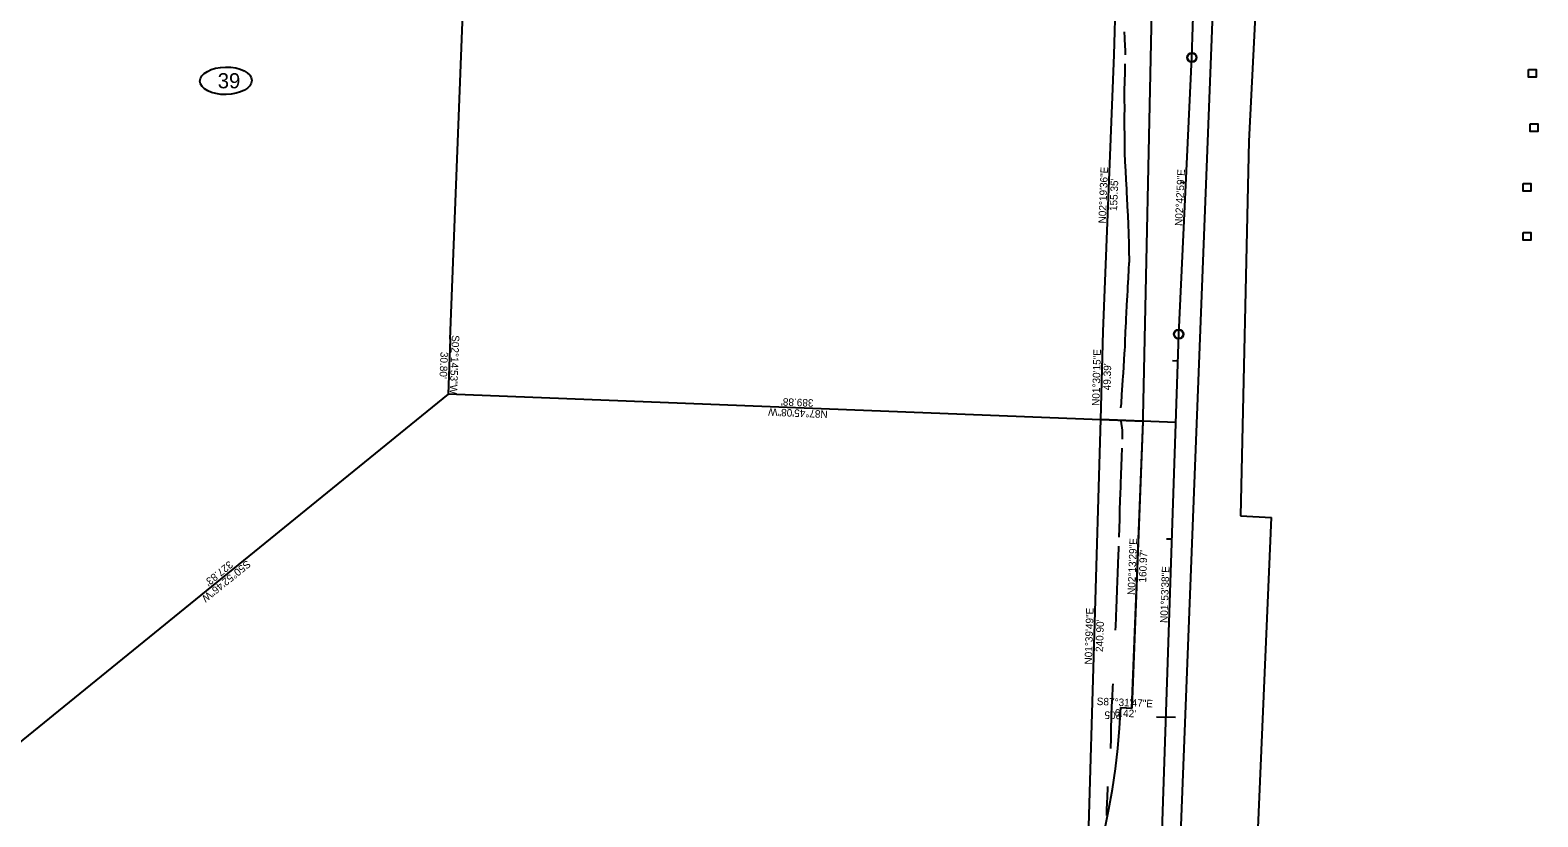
# Model space of a CAD drawing. Extents: x 1145508 to 2262867, y -3126236 to 2021677.
# Drawn here: x 1151042 to 1151887, y 2019521 to 2019963 of the extents above; entities that cross this region are included whole.
import ezdxf

# ---------------------------------------------------------------- set-up
doc = ezdxf.new("R2010")
doc.units = 0
for name, color, linetype in [('DSN_RDWY_Alignment', 7, 'Continuous'), ('DSN_RDWY_Alignment Annotation', 7, 'Continuous'), ('DSN_RDWY_Const Limits', 7, 'Continuous'), ('DSN_ROW_Annotation', 7, 'Continuous'), ('DSN_ROW_Esmnt', 7, 'Continuous'), ('DSN_ROW_Line-Annotation', 7, 'Continuous'), ('DSN_ROW_Prop-Line', 7, 'Continuous'), ('E_Const Align', 7, 'Continuous'), ('EX_PROPERTY', 7, 'Continuous'), ('EX_ROW', 7, 'Continuous'), ('EX_ROW_ANNOT', 7, 'Continuous'), ('EX_SECTION', 7, 'Continuous')]:
    doc.layers.add(name, color=color, linetype=linetype)

msp = doc.modelspace()

# ---------------------------------------------------------------- linework, layer by layer
at = {"layer": 'DSN_RDWY_Alignment'}
for centre in [(1151693.25, 2019947.42), (1151685.88, 2019792.22)]:
    msp.add_circle(centre, 2.5, dxfattribs=at)
at = {"layer": 'DSN_RDWY_Alignment Annotation'}
for p, q in [((1151693.25, 2019947.42), (1151693.25, 2019947.42)), ((1151686.92, 2019877.38), (1151689.92, 2019877.24)), ((1151685.88, 2019792.22), (1151685.88, 2019792.22)), ((1151682.39, 2019777.44), (1151685.39, 2019777.34)), ((1151679.09, 2019677.49), (1151682.09, 2019677.4)), ((1151673.45, 2019577.63), (1151684.06, 2019577.28))]:
    msp.add_line(p, q, dxfattribs=at)
for centre in [(1151693.25, 2019947.42), (1151685.88, 2019792.22)]:
    msp.add_circle(centre, 2.67, dxfattribs=at)
at = {"layer": 'DSN_RDWY_Const Limits'}
for points in [[(1151656.11, 2019948.92), (1151656.1, 2019949.18), (1151655.97, 2019951.85), (1151655.96, 2019952.12), (1151655.91, 2019953.37), (1151655.61, 2019958.38), (1151655.45, 2019961.72)], [(1151653.4, 2019750.97), (1151653.73, 2019753.37), (1151654.04, 2019758.37), (1151654.35, 2019763.36), (1151654.59, 2019766.67), (1151654.6, 2019766.87), (1151654.72, 2019768.35), (1151655.06, 2019773.34), (1151655.37, 2019778.33), (1151655.67, 2019783.33), (1151655.77, 2019784.96), (1151655.77, 2019785.18), (1151655.85, 2019788.32), (1151656.04, 2019793.21), (1151656.07, 2019793.75), (1151656.35, 2019798.74), (1151656.48, 2019801.11), (1151656.48, 2019801.14), (1151656.59, 2019803.73), (1151656.87, 2019808.73), (1151657.15, 2019813.72), (1151657.31, 2019816.62), (1151657.33, 2019817.05), (1151657.43, 2019818.71), (1151657.71, 2019823.7), (1151657.99, 2019828.7), (1151658.18, 2019832.12), (1151658.22, 2019832.96), (1151658.26, 2019833.69), (1151658.15, 2019838.7), (1151658.04, 2019843.71), (1151657.95, 2019847.67), (1151657.91, 2019848.72), (1151657.91, 2019848.93), (1151657.68, 2019853.74), (1151657.45, 2019858.76), (1151657.22, 2019863.77), (1151656.98, 2019868.79), (1151656.84, 2019871.33), (1151656.81, 2019871.84), (1151656.72, 2019873.81), (1151656.46, 2019878.82), (1151656.21, 2019883.84), (1151655.95, 2019888.86), (1151655.68, 2019893.88), (1151655.65, 2019894.76), (1151655.65, 2019895), (1151655.69, 2019898.88), (1151655.73, 2019903.89), (1151655.54, 2019908.9), (1151655.44, 2019911.38), (1151655.44, 2019913.91), (1151655.44, 2019914.38), (1151655.59, 2019918.91), (1151655.57, 2019923.92), (1151655.5, 2019927.66), (1151655.5, 2019927.75), (1151655.49, 2019928.93), (1151655.72, 2019933.92), (1151655.79, 2019938.92), (1151655.88, 2019943.93)], [(1151654.4, 2019733.34), (1151654.39, 2019734.05), (1151654.37, 2019735.03), (1151654.32, 2019738.35), (1151653.68, 2019743.37)], [(1151652.58, 2019678.37), (1151652.68, 2019683.37), (1151652.79, 2019688.37), (1151652.85, 2019691.86), (1151652.88, 2019693.37), (1151652.89, 2019693.96), (1151653.06, 2019698.37), (1151653.27, 2019703.36), (1151653.37, 2019705.92), (1151653.45, 2019707.65), (1151653.48, 2019708.36), (1151653.66, 2019713.36), (1151653.82, 2019718.35), (1151653.87, 2019719.98), (1151653.91, 2019721.34), (1151653.97, 2019723.35), (1151654.15, 2019728.35)], [(1151650.49, 2019626.22), (1151650.57, 2019628.41), (1151650.79, 2019633.31), (1151650.79, 2019633.41), (1151650.83, 2019634.15), (1151651.02, 2019638.4), (1151651.22, 2019643.4), (1151651.41, 2019648.39), (1151651.46, 2019649.45), (1151651.61, 2019652.82), (1151651.63, 2019653.39), (1151651.8, 2019658.39), (1151651.94, 2019663.38), (1151652.16, 2019668.38), (1151652.3, 2019671.7), (1151652.33, 2019672.34), (1151652.38, 2019673.38)], [(1151647.88, 2019559.77), (1151647.92, 2019561.88), (1151647.96, 2019563.46), (1151648.03, 2019568.46), (1151648.1, 2019573.46), (1151648.12, 2019574.78), (1151648.14, 2019575.59), (1151648.18, 2019578.46), (1151648.41, 2019583.46), (1151648.69, 2019588.45), (1151648.73, 2019589.29), (1151648.92, 2019593.45), (1151648.96, 2019594.29), (1151649.05, 2019596.13)], [(1151645.67, 2019522.12), (1151645.67, 2019523.52), (1151645.67, 2019526.2), (1151645.74, 2019528.52), (1151645.97, 2019533.51), (1151646.03, 2019534.51), (1151646.09, 2019535.78), (1151646.2, 2019538.51)]]:
    msp.add_lwpolyline(points, dxfattribs=at)
at = {"layer": 'DSN_ROW_Esmnt'}
for p, q in [((1151649.76, 2019948.86), (1151655.32, 2020166.93)), ((1151643.45, 2019793.64), (1151649.76, 2019948.86)), ((1151642.15, 2019744.26), (1151643.45, 2019793.64)), ((1151635.16, 2019503.46), (1151642.15, 2019744.26))]:
    msp.add_line(p, q, dxfattribs=at)
for points in [[(1151881.83, 2019940.74), (1151886.15, 2019940.74), (1151886.15, 2019936.42), (1151881.83, 2019936.42)], [(1151882.82, 2019910.24), (1151887.14, 2019910.24), (1151887.14, 2019905.92), (1151882.82, 2019905.92)], [(1151878.89, 2019876.79), (1151883.21, 2019876.79), (1151883.21, 2019872.47), (1151878.89, 2019872.47)], [(1151878.89, 2019849.24), (1151883.21, 2019849.24), (1151883.21, 2019844.92), (1151878.89, 2019844.92)]]:
    msp.add_lwpolyline(points, close=True, dxfattribs=at)
msp.add_arc((1151252.74, 2019600.34), 401, 305.53912, 357.4811, dxfattribs=at)
at = {"layer": 'DSN_ROW_Line-Annotation'}
msp.add_ellipse((1151151.87, 2019934.33), major_axis=(14.54, 0.23), ratio=0.529773, dxfattribs=at)
at = {"layer": 'DSN_ROW_Prop-Line'}
for q in [(1151292.92, 2020180.46), (1151276.36, 2019758.62)]:
    msp.add_line((1151277.57, 2019789.4), q, dxfattribs=at)
at = {"layer": 'E_Const Align'}
for p, q in [((1151693.25, 2019947.42), (1151701.6, 2020205.53)), ((1151685.88, 2019792.22), (1151693.25, 2019947.42)), ((1151676.29, 2019502.1), (1151685.88, 2019792.22)), ((1151684.24, 2019742.63), (1151642.15, 2019744.26))]:
    msp.add_line(p, q, dxfattribs=at)
at = {"layer": 'EX_PROPERTY'}
for p, q in [((1151276.43, 2019758.58), (1151022.1, 2019551.74)), ((1151666.01, 2019743.29), (1151276.43, 2019758.58)), ((1151659.76, 2019582.44), (1151666.01, 2019743.29)), ((1151653.35, 2019582.72), (1151659.76, 2019582.44))]:
    msp.add_line(p, q, dxfattribs=at)
msp.add_arc((1151252.74, 2019600.34), 401, 305.53912, 357.4811, dxfattribs=at)
at = {"layer": 'EX_ROW'}
for p, q in [((1151666.04, 2019745.81), (1151674.8, 2020166.2)), ((1151738.18, 2020161.01), (1151725.1, 2019900.39)), ((1151725.1, 2019900.39), (1151720.55, 2019690.3)), ((1151659.69, 2019582.47), (1151665.94, 2019743.33)), ((1151665.94, 2019743.33), (1151666.04, 2019745.81)), ((1151702.36, 2018862.94), (1151737.94, 2019689.31)), ((1151720.55, 2019690.3), (1151737.94, 2019689.31)), ((1151653.28, 2019582.75), (1151659.69, 2019582.47))]:
    msp.add_line(p, q, dxfattribs=at)
at = {"layer": 'EX_SECTION'}
msp.add_line((1151660.65, 2018840.69), (1151712.63, 2020164.79), dxfattribs=at)

# ---------------------------------------------------------------- texts
at = {"layer": 'DSN_RDWY_Alignment Annotation'}
for s, rotation, p in [('N02°42\'59"E', 87.28371, (1151687.86, 2019852.83)), ('N01°53\'38"E', 88.10599, (1151679.62, 2019630.14)), ('205', 178.10599, (1151653.69, 2019580.38))]:
    msp.add_text(s, height=4.2, rotation=rotation, dxfattribs=at).set_placement(p)
at = {"layer": 'DSN_ROW_Annotation'}
for s, rotation, p in [('N02°19\'36"E', 87.67344, (1151645.01, 2019854.24)), ("155.35'", 87.67344, (1151651.3, 2019861.19)), ('S02°14\'53"W', 267.752, (1151278.56, 2019791.73)), ('N01°30\'15"E', 88.49572, (1151641.45, 2019751.92)), ("30.80'", 267.752, (1151272.19, 2019782.35)), ("49.39'", 88.49572, (1151647.68, 2019760.67)), ('N01°39\'49"E', 88.33652, (1151637.26, 2019606.84)), ("240.90'", 88.33652, (1151643.47, 2019613.86))]:
    msp.add_text(s, height=4.2, rotation=rotation, dxfattribs=at).set_placement(p)
at = {"layer": 'DSN_ROW_Line-Annotation'}
msp.add_text('39', height=8.5, dxfattribs=at).set_placement((1151147.31, 2019930.12))
at = {"layer": 'EX_ROW_ANNOT'}
for s, rotation, p in [('N87°45\'08"W', 177.75219, (1151489.24, 2019749.33)), ("389.88'", 177.75219, (1151481.27, 2019755.65)), ('N02°13\'29"E', 87.77532, (1151661.33, 2019645.86)), ('S50°52\'46"W', 219.12061, (1151163.62, 2019665.67)), ("160.97'", 87.77532, (1151667.6, 2019652.82)), ("327.83'", 219.12061, (1151153.69, 2019665.34)), ('S87°31\'47"E', 357.52971, (1151639.85, 2019584.2)), ("6.42'", 357.52971, (1151649.9, 2019577.76))]:
    msp.add_text(s, height=4.2, rotation=rotation, dxfattribs=at).set_placement(p)

doc.saveas('drawing.dxf')
